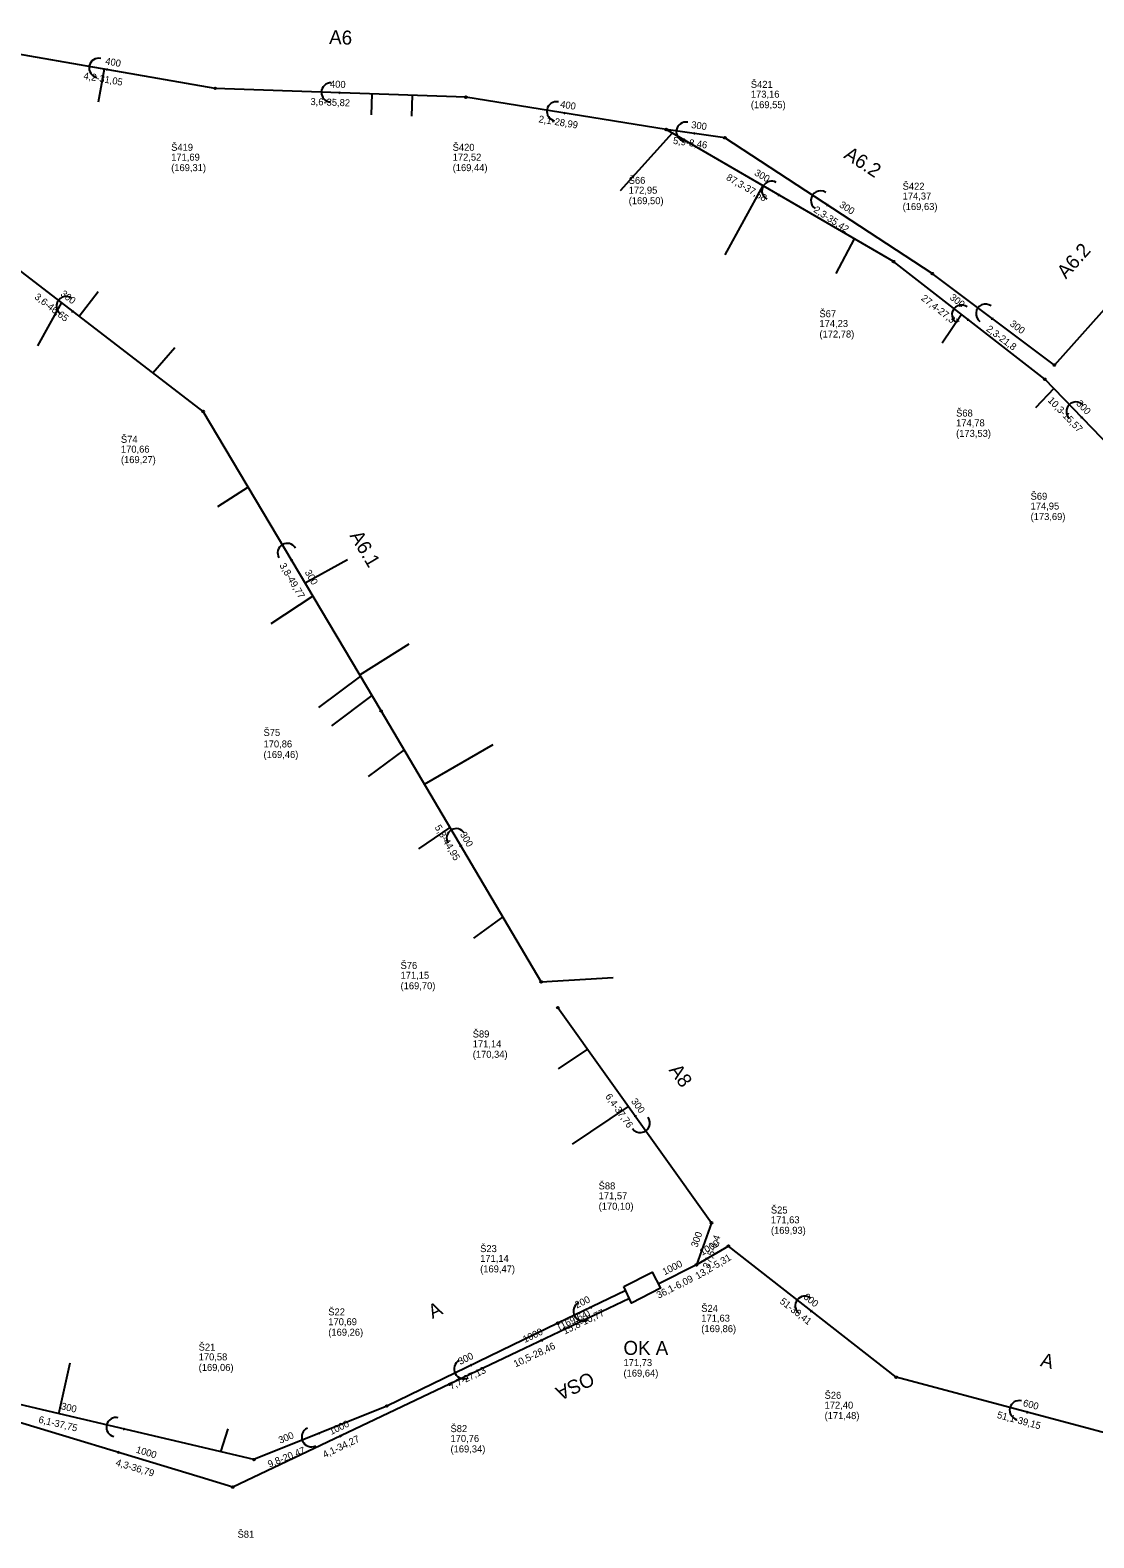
# Model space of a CAD drawing. Extents: x -548529 to -543591, y -1201432 to -1192608.
# Drawn here: x -546963.8 to -546811.8, y -1194989.7 to -1194774.4 of the extents above; entities that cross this region are included whole.
import ezdxf

# ---------------------------------------------------------------- set-up
doc = ezdxf.new("R2010")
doc.units = 0
for name, color, linetype in [('C3D_Bod-Značky', 7, 'Continuous'), ('C3D_Koridor', 7, 'Continuous'), ('C3D_Křižovatka', 7, 'Continuous'), ('C3D_Netisknutelná', 7, 'Continuous'), ('C3D_Povrch-Vrstevnice', 7, 'Continuous'), ('C3D_PP-Navrh', 7, 'Continuous'), ('C3D_PP-Popisek', 7, 'Continuous'), ('C3D_PP-zobrazeni v PR', 7, 'Continuous'), ('C3D_PR-Popisek', 7, 'Continuous'), ('C3D_SPR-Popisek', 7, 'Continuous'), ('C3D_Tlakove_potrubi_Popis', 7, 'Continuous'), ('C3D_ZPR-Formaty', 7, 'Continuous')]:
    doc.layers.add(name, color=color, linetype=linetype)

# ---------------------------------------------------------------- blocks, each defined once
blk = doc.blocks.new('100')
at = {"layer": 'Defpoints'}
blk.add_circle((0, 0), 0.127, dxfattribs=at)
blk = doc.blocks.new('92')
at = {"layer": 'Defpoints'}
for points in [[(-0.11, 0.138), (0, 0), (-0.11, -0.136)], [(0.039, 0.138), (0.149, 0), (0.039, -0.136)]]:
    blk.add_lwpolyline(points, dxfattribs=at)
blk = doc.blocks.new('86')
at = {"layer": 'Defpoints'}
blk.add_lwpolyline([(0.08, 0.14), (0.19, 0), (0.08, -0.14)], dxfattribs=at)
blk.add_arc((1.37, 0), 1.37, 270, 90, dxfattribs=at)
blk = doc.blocks.new('91')
at = {"layer": 'Defpoints'}
blk.add_lwpolyline([(0.08, 0.14), (0.19, 0), (0.08, -0.14)], dxfattribs=at)
blk.add_arc((1.37, 0), 1.37, 270, 90, dxfattribs=at)

msp = doc.modelspace()

# ---------------------------------------------------------------- linework, layer by layer
at = {"layer": 'C3D_Bod-Značky'}
for points in [[(-546937.35, -1194782.69), (-546967.94, -1194777.39)], [(-546901.55, -1194783.94), (-546937.35, -1194782.69)], [(-546872.93, -1194788.56), (-546901.55, -1194783.94)], [(-546840.438, -1194807.434), (-546872.93, -1194788.56)], [(-546864.55, -1194789.74), (-546872.93, -1194788.56)], [(-546834.91, -1194809.14), (-546864.55, -1194789.74)], [(-546939.08, -1194828.823), (-546976.071, -1194800.407)], [(-546799.24, -1194801.84), (-546817.46, -1194822.21)], [(-546818.831, -1194824.231), (-546840.438, -1194807.434)], [(-546817.46, -1194822.21), (-546834.91, -1194809.14)], [(-546807.989, -1194835.403), (-546818.831, -1194824.231)], [(-546913.657, -1194871.608), (-546939.08, -1194828.823)], [(-546890.778, -1194910.301), (-546913.657, -1194871.608)], [(-546888.413, -1194913.979), (-546866.453, -1194944.697)], [(-546866.453, -1194944.697), (-546868.61, -1194950.722)], [(-546864.03, -1194948.027), (-546868.61, -1194950.722)], [(-546840.07, -1194966.76), (-546864.03, -1194948.027)], [(-546868.61, -1194950.722), (-546874.055, -1194953.453)], [(-546878.709, -1194954.38), (-546888.413, -1194959.041)], [(-546888.413, -1194959.041), (-546912.83, -1194970.87)], [(-546802.25, -1194976.86), (-546840.07, -1194966.76)], [(-546931.82, -1194978.525), (-546968.576, -1194969.904)], [(-546912.83, -1194970.87), (-546931.82, -1194978.525)]]:
    msp.add_lwpolyline(points, dxfattribs=at)
at = {"layer": 'C3D_Koridor'}
for points in [[(-546953.243, -1194779.936), (-546954.076, -1194784.67)], [(-546914.984, -1194783.471), (-546915.088, -1194786.469)], [(-546909.227, -1194783.672), (-546909.332, -1194786.67)], [(-546872.057, -1194789.067), (-546879.491, -1194797.329)], [(-546859.118, -1194796.583), (-546864.522, -1194806.447)], [(-546846.079, -1194804.157), (-546848.676, -1194809.152)], [(-546956.774, -1194815.231), (-546954.092, -1194811.716)], [(-546959.321, -1194813.274), (-546962.743, -1194819.442)], [(-546830.72, -1194814.989), (-546833.5, -1194819.083)], [(-546946.275, -1194823.296), (-546943.149, -1194819.721)], [(-546817.556, -1194825.545), (-546820.137, -1194828.3)], [(-546932.641, -1194839.66), (-546937.048, -1194842.463)], [(-546924.522, -1194853.324), (-546918.476, -1194849.993)], [(-546923.407, -1194855.199), (-546929.39, -1194859.147)], [(-546916.717, -1194866.458), (-546909.631, -1194862.005)], [(-546916.614, -1194866.632), (-546922.62, -1194871.112)], [(-546914.958, -1194869.418), (-546920.76, -1194873.712)], [(-546910.369, -1194877.168), (-546915.495, -1194880.958)], [(-546907.469, -1194882.073), (-546897.652, -1194876.408)], [(-546903.82, -1194888.245), (-546908.307, -1194891.273)], [(-546896.265, -1194901.022), (-546900.455, -1194904.032)], [(-546890.778, -1194910.301), (-546880.522, -1194909.653)], [(-546884.188, -1194919.896), (-546888.36, -1194922.721)], [(-546878.335, -1194928.078), (-546886.356, -1194933.451)], [(-546959.692, -1194971.988), (-546958.103, -1194964.704)], [(-546936.544, -1194977.417), (-546935.487, -1194974.148)]]:
    msp.add_lwpolyline(points, dxfattribs=at)
at = {"layer": 'C3D_Povrch-Vrstevnice'}
for points in [[(-546878.185, -1194955.53), (-546893.148, -1194962.658), (-546903.88, -1194967.77)], [(-546903.88, -1194967.77), (-546934.854, -1194982.443)], [(-546934.854, -1194982.443), (-546939.511, -1194981.036), (-546970.068, -1194971.803)]]:
    msp.add_lwpolyline(points, dxfattribs=at)
at = {"layer": 'C3D_PP-Navrh'}
msp.add_lwpolyline([(-546878.966, -1194953.816), (-546874.908, -1194951.765), (-546873.747, -1194954.061), (-546877.898, -1194956.159), (-546878.966, -1194953.816)], dxfattribs=at)

# ---------------------------------------------------------------- block references
at = {"layer": 'C3D_PP-zobrazeni v PR'}
for p, xscale, yscale, rotation in [((-546937.35, -1194782.69), 1.0018265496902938, 1.0018265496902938, -6.078126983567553), ((-546901.55, -1194783.94), 1.0018265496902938, 1.0018265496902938, -6.078126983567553), ((-546872.93, -1194788.56), 1.0316957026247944, 1.0316957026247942, -23.584588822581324), ((-546864.55, -1194789.74), 1.0296949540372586, 1.0296949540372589, -24.133790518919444), ((-546840.438, -1194807.434), 0.9999999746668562, 0.999999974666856, -34.00000045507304), ((-546834.91, -1194809.14), 1.000000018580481, 1.000000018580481, -35.000000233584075), ((-546817.46, -1194822.21), 1.0011217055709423, 1.0011217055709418, 6.582609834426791), ((-546818.831, -1194824.231), 1.0000000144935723, 1.0000000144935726, 139.00000089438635), ((-546939.08, -1194828.823), 1.0000000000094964, 1.0000000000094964, 132.0000013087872), ((-546913.657, -1194871.608), 1.0000000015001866, 1.0000000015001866, 120.99999982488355), ((-546890.778, -1194910.301), 1.0000000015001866, 1.0000000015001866, -59.00000017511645), ((-546888.413, -1194913.979), 1.000000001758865, 1.000000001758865, 125.99999933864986), ((-546866.453, -1194944.697), 0.9999999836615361, 0.9999999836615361, -81.99999961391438), ((-546864.03, -1194948.027), 1.0002788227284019, 1.0002788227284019, 176.70930040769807), ((-546868.61, -1194950.722), 1.000000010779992, 1.0000000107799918, 141.00000108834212), ((-546888.413, -1194959.041), 1.0138865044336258, 1.0138865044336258, -152.43468640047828), ((-546840.07, -1194966.76), 1.0138865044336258, 1.0138865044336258, 152.43468640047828), ((-546903.88, -1194967.77), 1.0138865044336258, 1.0138865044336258, -152.43468640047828), ((-546912.83, -1194970.87), 1.019856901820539, 1.0198569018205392, -153.606016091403), ((-546931.82, -1194978.525), 1.0018265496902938, 1.0018265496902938, -173.92187301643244), ((-546934.854, -1194982.443), 1.0018265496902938, 1.0018265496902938, -173.92187301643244)]:
    msp.add_blockref('100', p, dxfattribs=dict(at, xscale=xscale, yscale=yscale, rotation=rotation))
at = {"layer": 'C3D_SPR-Popisek'}
for name, p, xscale, yscale, rotation in [('86', (-546952.645, -1194780.04), 1.008377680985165, 1.0083776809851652, 168.37362119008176), ('86', (-546919.45, -1194783.315), 1.00000001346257, 1.0000000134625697, 178.0000000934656), ('86', (-546887.24, -1194786.25), 1.008377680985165, 1.0083776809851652, 168.37362119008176), ('86', (-546868.74, -1194789.15), 1.0092050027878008, 1.0092050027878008, 168.88308178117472), ('91', (-546856.684, -1194797.997), 0.9999999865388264, 0.9999999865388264, 149.99999955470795), ('86', (-546849.73, -1194799.44), 0.9999999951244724, 0.9999999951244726, 146.99999872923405), ('91', (-546957.576, -1194814.615), 0.9999999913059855, 0.9999999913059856, 142.99999806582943), ('91', (-546829.634, -1194815.832), 0.9999999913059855, 0.9999999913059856, 142.99999806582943), ('86', (-546826.185, -1194815.675), 1.000000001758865, 1.000000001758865, 144.00000066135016), ('91', (-546813.41, -1194829.817), 0.999999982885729, 0.9999999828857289, 135), ('91', (-546926.368, -1194850.216), 1.0000000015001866, 1.0000000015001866, 120.99999982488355), ('91', (-546902.218, -1194890.954), 1.0000000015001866, 1.0000000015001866, 120.99999982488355), ('91', (-546877.433, -1194929.338), 1.000000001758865, 1.000000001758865, -54.00000066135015), ('86', (-546883.561, -1194956.71), 1.0138865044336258, 1.0138865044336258, -152.43468640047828), ('91', (-546852.05, -1194957.394), 1.000000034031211, 1.0000000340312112, 141.99999959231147), ('92', (-546890.645, -1194961.465), 1.0138865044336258, 1.0138865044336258, -152.43468640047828), ('86', (-546900.621, -1194964.956), 1.0138865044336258, 1.0138865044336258, -152.43468640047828), ('91', (-546821.16, -1194971.81), 1.0009848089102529, 1.000984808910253, 165.77567372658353), ('86', (-546950.198, -1194974.214), 1.0028916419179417, 1.0028916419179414, 166.30279126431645), ('86', (-546922.325, -1194974.698), 1.025136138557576, 1.025136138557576, -154.7492415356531), ('92', (-546919.367, -1194975.106), 1.0138865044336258, 1.0138865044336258, -152.43468640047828), ('92', (-546951.112, -1194977.531), 1.0365458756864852, 1.0365458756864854, 158.02850914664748)]:
    msp.add_blockref(name, p, dxfattribs=dict(at, xscale=xscale, yscale=yscale, rotation=rotation))

# ---------------------------------------------------------------- texts
at = {"layer": 'C3D_Křižovatka'}
for s, p in [('Š421', (-546860.83, -1194782.62)), ('Š419', (-546943.65, -1194791.61)), ('Š420', (-546903.43, -1194791.61)), ('Š66', (-546878.28, -1194796.33)), ('Š422', (-546839.14, -1194797.17)), ('Š67', (-546851.028, -1194815.374)), ('Š68', (-546831.501, -1194829.561)), ('Š74', (-546950.83, -1194833.313)), ('Š69', (-546820.859, -1194841.443)), ('Š75', (-546930.457, -1194875.188)), ('Š76', (-546910.878, -1194908.451)), ('Š89', (-546900.563, -1194918.239)), ('Š88', (-546882.573, -1194939.937)), ('Š25', (-546857.96, -1194943.377)), ('Š23', (-546899.503, -1194948.891)), ('Š22', (-546921.2, -1194957.93)), ('Š24', (-546867.91, -1194957.422)), ('Š21', (-546939.72, -1194962.955)), ('Š26', (-546850.29, -1194969.84)), ('Š82', (-546903.74, -1194974.6)), ('Š81', (-546934.164, -1194989.683))]:
    msp.add_text(s, height=1, dxfattribs=at).set_placement(p)
at = {"layer": 'C3D_Netisknutelná'}
for s, rotation, p in [('A6', 358, (-546921.096, -1194776.349)), ('A6.2', 326.79, (-546847.678, -1194792.535)), ('A6.2', 48.19, (-546815.802, -1194810.016)), ('A6.1', 300.72, (-546918.198, -1194846.571)), ('A8', 305.56, (-546872.6, -1194922.899)), ('A', 25.85, (-546906.314, -1194958.445)), ('A', 345.05, (-546819.574, -1194965.141)), ('OSA', 205.47, (-546883.811, -1194965.918))]:
    msp.add_text(s, height=2, rotation=rotation, dxfattribs=at).set_placement(p)
at = {"layer": 'C3D_PP-Popisek'}
for s, height, p in [('OK A', 2, (-546879.024, -1194963.569)), ('171,73 ', 1, (-546879.024, -1194965.169)), ('(169,64)', 1, (-546879.024, -1194966.669))]:
    msp.add_text(s, height=height, dxfattribs=at).set_placement(p)
at = {"layer": 'C3D_PR-Popisek'}
for s, rotation, p in [('400', 350.17, (-546953.122, -1194779.248)), ('400', 358, (-546920.971, -1194782.561)), ('400', 350.83, (-546888.122, -1194785.402)), ('300', 351.98, (-546869.399, -1194788.346)), ('300', 329.85, (-546860.415, -1194795.023)), ('300', 326.79, (-546848.279, -1194799.554)), ('300', 322.47, (-546959.545, -1194812.22)), ('300', 322.14, (-546832.498, -1194812.722)), ('300', 323.17, (-546823.915, -1194816.501)), ('300', 314.14, (-546814.413, -1194827.776)), ('300', 300.72, (-546924.61, -1194851.801)), ('300', 300.6, (-546902.432, -1194889.221)), ('300', 305.56, (-546877.987, -1194927.354)), ('300', 70.3, (-546868.487, -1194948.303)), ('1000', 30.47, (-546867.778, -1194949.423)), ('1000', 26.64, (-546873.155, -1194952.217)), ('200', 25.66, (-546885.691, -1194956.956)), ('600', 321.98, (-546853.407, -1194955.446)), ('1000', 25.47, (-546893.119, -1194961.868)), ('300', 25.85, (-546902.362, -1194965.02)), ('300', 346.8, (-546959.455, -1194971.322)), ('600', 345.05, (-546822.015, -1194970.86)), ('1000', 25.35, (-546920.796, -1194975.013)), ('300', 21.95, (-546928.084, -1194976.266)), ('1000', 343.19, (-546948.758, -1194977.511))]:
    msp.add_text(s, height=1, rotation=rotation, dxfattribs=at).set_placement(p)
at = {"layer": 'C3D_Tlakove_potrubi_Popis'}
for s, p in [('173,16 ', (-546860.83, -1194784.02)), ('(169,55)', (-546860.83, -1194785.52)), ('171,69 ', (-546943.65, -1194793.01)), ('172,52 ', (-546903.43, -1194793.01)), ('(169,31)', (-546943.65, -1194794.51)), ('(169,44)', (-546903.43, -1194794.51)), ('(169,50)', (-546878.28, -1194799.23)), ('172,95 ', (-546878.28, -1194797.73)), ('174,37 ', (-546839.14, -1194798.57)), ('(169,63)', (-546839.14, -1194800.07)), ('174,23 ', (-546851.028, -1194816.774)), ('(172,78)', (-546851.028, -1194818.274)), ('174,78 ', (-546831.501, -1194830.961)), ('(173,53)', (-546831.501, -1194832.461)), ('(169,27)', (-546950.83, -1194836.213)), ('170,66 ', (-546950.83, -1194834.713)), ('174,95 ', (-546820.859, -1194842.843)), ('(173,69)', (-546820.859, -1194844.343)), ('170,86 ', (-546930.457, -1194876.818)), ('(169,46)', (-546930.457, -1194878.318)), ('(169,70)', (-546910.878, -1194911.351)), ('171,15 ', (-546910.878, -1194909.851)), ('171,14 ', (-546900.563, -1194919.639)), ('(170,34)', (-546900.563, -1194921.139)), ('171,57 ', (-546882.573, -1194941.337)), ('(170,10)', (-546882.573, -1194942.837)), ('(169,93)', (-546857.96, -1194946.277)), ('171,63 ', (-546857.96, -1194944.777)), ('171,14 ', (-546899.503, -1194950.291)), ('(169,47)', (-546899.503, -1194951.791)), ('171,63 ', (-546867.91, -1194958.822)), ('(169,26)', (-546921.2, -1194960.83)), ('170,69 ', (-546921.2, -1194959.33)), ('(169,86)', (-546867.91, -1194960.322)), ('170,58 ', (-546939.72, -1194964.355)), ('(169,06)', (-546939.72, -1194965.855)), ('172,40 ', (-546850.29, -1194971.24)), ('(171,48)', (-546850.29, -1194972.74)), ('170,76 ', (-546903.74, -1194976)), ('(169,34)', (-546903.74, -1194977.5))]:
    msp.add_text(s, height=1, dxfattribs=at).set_placement(p)
at = {"layer": 'C3D_ZPR-Formaty'}
for s, rotation, p in [('4,2-31,05', 350.17, (-546956.231, -1194781.347)), ('3,6-35,82', 358, (-546923.758, -1194785.066)), ('2,1-28,99', 350.83, (-546891.2, -1194787.534)), ('5,9-8,46', 351.98, (-546871.992, -1194790.608)), ('87,3-37,58', 329.85, (-546864.442, -1194795.691)), ('2,3-35,42', 326.79, (-546851.955, -1194800.257)), ('3,6-46,65', 322.47, (-546963.269, -1194812.645)), ('27,4-27,37', 322.14, (-546836.584, -1194812.834)), ('2,3-21,8', 323.17, (-546827.275, -1194817.233)), ('10,3-15,57', 314.14, (-546818.471, -1194827.33)), ('3,8-49,77', 300.72, (-546928.223, -1194850.815)), ('5,3-44,95', 300.6, (-546906.042, -1194888.22)), ('6,4-37,76', 305.56, (-546881.677, -1194926.672)), ('37,5-6,4', 70.3, (-546866.798, -1194951.303)), ('13,2-5,31', 30.47, (-546868.397, -1194952.801)), ('36,1-6,09', 26.64, (-546874.008, -1194955.558)), ('51-30,41', 321.98, (-546856.782, -1194956.103)), ('  (169,64)   ', 25.47, (-546888.834, -1194960.381)), ('15,8-10,77', 25.66, (-546887.405, -1194960.662)), ('10,5-28,46', 25.47, (-546894.435, -1194965.373)), ('7,7-27,13', 25.85, (-546903.652, -1194968.537)), ('6,1-37,75', 346.8, (-546962.673, -1194973.238)), ('51,1-39,15', 345.05, (-546825.729, -1194972.559)), ('4,1-34,27', 25.35, (-546921.72, -1194978.321)), ('9,8-20,47', 21.95, (-546929.615, -1194979.684)), ('4,3-36,79', 343.19, (-546951.657, -1194979.35))]:
    msp.add_text(s, height=1, rotation=rotation, dxfattribs=at).set_placement(p)

doc.saveas('drawing.dxf')
